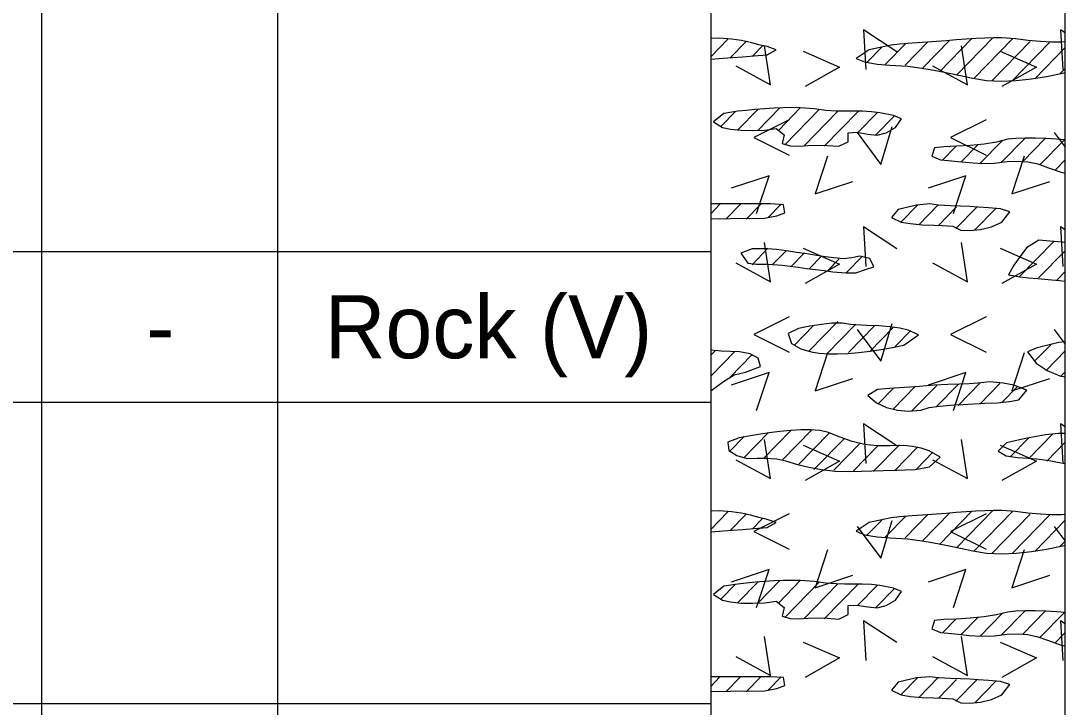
# Model space of a CAD drawing. Extents: x -0.01 to 0.83, y -0.63 to 1.27.
# Drawn here: x 0.7228 to 0.8333, y 0.0953 to 0.1679 of the extents above; entities that cross this region are included whole.
import ezdxf

# ---------------------------------------------------------------- set-up
doc = ezdxf.new("R2010")
doc.units = 0

msp = doc.modelspace()

# ---------------------------------------------------------------- linework, layer by layer
for points in [[(0, 0), (0.83333, 0), (0.83333, 1.275), (0, 1.275)], [(0, 0), (0.83333, 0), (0.83333, 1.275), (0, 1.275)], [(0, 0), (0.83333, 0), (0.83333, 1.275), (0, 1.275)], [(0, 0), (0.83333, 0), (0.83333, 1.275), (0, 1.275)], [(0, 0), (0.83333, 0), (0.83333, 1.275), (0, 1.275)], [(0.79583, 0.16382), (0.79715, 0.16393), (0.79814, 0.16401), (0.79922, 0.16408), (0.80039, 0.16417), (0.80179, 0.16429), (0.80275, 0.16481), (0.80179, 0.16515), (0.80091, 0.16536), (0.80003, 0.16558), (0.79909, 0.16579), (0.79803, 0.16595), (0.79677, 0.16605), (0.79583, 0.16603)], [(0.82816, 0.16158), (0.82978, 0.16174), (0.83137, 0.162), (0.8329, 0.16231), (0.83333, 0.16241), (0.83333, 0.16565), (0.83295, 0.16562), (0.83188, 0.16564), (0.83071, 0.16569), (0.82938, 0.1658), (0.82807, 0.16597), (0.82662, 0.16609), (0.82576, 0.16609), (0.82484, 0.16606), (0.82387, 0.16601), (0.82286, 0.16594), (0.82182, 0.16586), (0.82077, 0.16578), (0.81973, 0.1657), (0.81872, 0.16562), (0.81715, 0.16552), (0.81579, 0.16543), (0.81491, 0.1653), (0.81357, 0.16502), (0.8126, 0.16481), (0.81121, 0.16389), (0.8121, 0.16353), (0.81345, 0.16329), (0.81479, 0.1632), (0.81668, 0.16309), (0.81818, 0.16289), (0.81905, 0.16275), (0.82, 0.16257), (0.82107, 0.16235), (0.82225, 0.1621), (0.82357, 0.16181), (0.82501, 0.16158), (0.82656, 0.16151)], [(0.79708, 0.15659), (0.79794, 0.15642), (0.79904, 0.1563), (0.80028, 0.15627), (0.80156, 0.15632), (0.80274, 0.15648), (0.80361, 0.15582), (0.80338, 0.15492), (0.80422, 0.15465), (0.80517, 0.15463), (0.80613, 0.15469), (0.8072, 0.15472), (0.80818, 0.15469), (0.80939, 0.15461), (0.81037, 0.15508), (0.81038, 0.15603), (0.8113, 0.15609), (0.81244, 0.1559), (0.81346, 0.1558), (0.81438, 0.15605), (0.81539, 0.15659), (0.81601, 0.15751), (0.81517, 0.15788), (0.81374, 0.15815), (0.81285, 0.15825), (0.81187, 0.15831), (0.81, 0.15831), (0.8091, 0.15833), (0.808, 0.1584), (0.80678, 0.15856), (0.8053, 0.15869), (0.80443, 0.1587), (0.80349, 0.15868), (0.80251, 0.15864), (0.80152, 0.15858), (0.80054, 0.1585), (0.79959, 0.15841), (0.7987, 0.15831), (0.79722, 0.15809), (0.79614, 0.15721)], [(0.83241, 0.15537), (0.83129, 0.15544), (0.83017, 0.15548), (0.8291, 0.15548), (0.82811, 0.15544), (0.82728, 0.15535), (0.82608, 0.15505), (0.82476, 0.15483), (0.8233, 0.15469), (0.82183, 0.15461), (0.82051, 0.15455), (0.81951, 0.15445), (0.81922, 0.15358), (0.82013, 0.15317), (0.82097, 0.15311), (0.822, 0.15301), (0.82318, 0.15288), (0.82448, 0.1528), (0.82584, 0.15282), (0.82719, 0.15299), (0.82836, 0.15305), (0.8294, 0.15297), (0.83043, 0.15274), (0.83156, 0.15235), (0.83291, 0.15186), (0.83333, 0.15178), (0.83333, 0.1553)], [(0.79583, 0.14696), (0.79676, 0.14695), (0.79792, 0.14697), (0.79882, 0.14701), (0.79992, 0.14697), (0.80151, 0.14701), (0.80282, 0.14727), (0.80367, 0.14759), (0.80354, 0.14843), (0.80216, 0.14851), (0.79583, 0.14851)], [(0.81822, 0.14632), (0.81944, 0.14626), (0.82033, 0.14622), (0.82145, 0.14615), (0.82229, 0.14574), (0.82324, 0.14569), (0.82438, 0.1458), (0.82555, 0.14609), (0.82662, 0.14659), (0.82749, 0.14769), (0.82651, 0.14799), (0.82524, 0.14809), (0.82413, 0.14816), (0.82324, 0.14826), (0.82226, 0.14828), (0.82121, 0.1483), (0.81995, 0.1484), (0.81902, 0.14851), (0.81761, 0.14837), (0.81566, 0.14793), (0.81496, 0.14709), (0.81598, 0.1466), (0.81695, 0.14643)], [(0.80066, 0.14216), (0.80188, 0.14215), (0.80339, 0.14203), (0.80423, 0.14193), (0.8051, 0.14182), (0.806, 0.1417), (0.80692, 0.14158), (0.80784, 0.14146), (0.80875, 0.14135), (0.81014, 0.14121), (0.81119, 0.14122), (0.81222, 0.14157), (0.81308, 0.14185), (0.81267, 0.14275), (0.8116, 0.143), (0.81075, 0.1428), (0.80989, 0.14272), (0.80885, 0.1428), (0.80799, 0.14291), (0.80703, 0.14306), (0.806, 0.14322), (0.80492, 0.14339), (0.80384, 0.14354), (0.8028, 0.14368), (0.80182, 0.14377), (0.8002, 0.14378), (0.79901, 0.1433), (0.79974, 0.14226)], [(0.83305, 0.14446), (0.83171, 0.14458), (0.83054, 0.14468), (0.82925, 0.14386), (0.82857, 0.14294), (0.82792, 0.14205), (0.82735, 0.14103), (0.82858, 0.1408), (0.82945, 0.1407), (0.83045, 0.14061), (0.83155, 0.14051), (0.83272, 0.14041), (0.83333, 0.14036), (0.83333, 0.14445)], [(0.81233, 0.13565), (0.81063, 0.13577), (0.80977, 0.13591), (0.8086, 0.13591), (0.80755, 0.13577), (0.80632, 0.13557), (0.80513, 0.13533), (0.80403, 0.13481), (0.80436, 0.13375), (0.80536, 0.13318), (0.80647, 0.13288), (0.8073, 0.13273), (0.80824, 0.13265), (0.80926, 0.13265), (0.81035, 0.1327), (0.81149, 0.1328), (0.81267, 0.13295), (0.81386, 0.13313), (0.81506, 0.13334), (0.81625, 0.13358), (0.81783, 0.13466), (0.81673, 0.13516), (0.81585, 0.13536), (0.8148, 0.13552), (0.81361, 0.13562)], [(0.83265, 0.13384), (0.83136, 0.13353), (0.83028, 0.13326), (0.82934, 0.13286), (0.83026, 0.13166), (0.83142, 0.1309), (0.83279, 0.13032), (0.83333, 0.13022), (0.83333, 0.13393)], [(0.79583, 0.12875), (0.79719, 0.12974), (0.79831, 0.13044), (0.79951, 0.13071), (0.80111, 0.13131), (0.80086, 0.13219), (0.80002, 0.13267), (0.79889, 0.13286), (0.79791, 0.13289), (0.79694, 0.13295), (0.79583, 0.13303)], [(0.82537, 0.12969), (0.82408, 0.12954), (0.82319, 0.12948), (0.82214, 0.12946), (0.82091, 0.12942), (0.81947, 0.12933), (0.81792, 0.12921), (0.81632, 0.12909), (0.81475, 0.129), (0.81348, 0.1289), (0.81247, 0.12826), (0.81337, 0.12749), (0.81444, 0.12699), (0.81561, 0.1267), (0.81675, 0.1266), (0.81807, 0.12671), (0.81896, 0.12698), (0.82003, 0.12713), (0.82157, 0.12725), (0.82253, 0.12731), (0.82362, 0.12737), (0.82483, 0.12743), (0.82618, 0.12749), (0.82745, 0.1276), (0.82842, 0.12778), (0.82927, 0.12883), (0.82791, 0.12935), (0.82679, 0.12955)], [(0.79885, 0.12378), (0.79763, 0.12332), (0.79773, 0.12242), (0.79859, 0.1219), (0.7997, 0.1216), (0.80074, 0.12161), (0.80165, 0.12163), (0.80281, 0.12154), (0.80377, 0.12134), (0.80486, 0.12099), (0.80606, 0.12069), (0.80751, 0.12042), (0.80905, 0.12023), (0.81052, 0.1202), (0.81177, 0.12026), (0.81289, 0.1203), (0.81408, 0.12033), (0.81553, 0.12037), (0.81642, 0.1204), (0.81745, 0.12043), (0.81897, 0.12071), (0.82011, 0.12174), (0.81896, 0.12241), (0.8181, 0.12268), (0.81717, 0.12287), (0.81626, 0.12298), (0.81479, 0.12292), (0.81343, 0.12292), (0.8121, 0.12307), (0.8108, 0.12338), (0.80953, 0.12384), (0.8082, 0.12439), (0.80736, 0.12455), (0.8064, 0.12462), (0.80536, 0.12462), (0.80427, 0.12456), (0.80314, 0.12445), (0.80201, 0.12431), (0.8009, 0.12414), (0.79984, 0.12396)], [(0.83263, 0.12423), (0.83126, 0.12409), (0.82969, 0.12382), (0.82883, 0.12365), (0.82712, 0.12324), (0.82623, 0.12237), (0.82708, 0.12188), (0.82831, 0.12169), (0.82941, 0.12163), (0.83033, 0.12154), (0.83165, 0.12136), (0.83253, 0.12121), (0.83333, 0.12107), (0.83333, 0.12422)], [(0.79583, 0.11382), (0.79715, 0.11393), (0.79814, 0.11401), (0.79922, 0.11408), (0.80039, 0.11417), (0.80179, 0.11429), (0.80275, 0.11481), (0.80179, 0.11515), (0.80091, 0.11536), (0.80003, 0.11558), (0.79909, 0.11579), (0.79803, 0.11595), (0.79677, 0.11605), (0.79583, 0.11603)], [(0.82816, 0.11158), (0.82978, 0.11174), (0.83137, 0.112), (0.8329, 0.11231), (0.83333, 0.11241), (0.83333, 0.11565), (0.83295, 0.11562), (0.83188, 0.11564), (0.83071, 0.11569), (0.82938, 0.1158), (0.82807, 0.11597), (0.82662, 0.11609), (0.82576, 0.11609), (0.82484, 0.11606), (0.82387, 0.11601), (0.82286, 0.11594), (0.82182, 0.11586), (0.82077, 0.11578), (0.81973, 0.1157), (0.81872, 0.11562), (0.81715, 0.11552), (0.81579, 0.11543), (0.81491, 0.1153), (0.81357, 0.11502), (0.8126, 0.11481), (0.81121, 0.11389), (0.8121, 0.11353), (0.81345, 0.11329), (0.81479, 0.1132), (0.81668, 0.11309), (0.81818, 0.11289), (0.81905, 0.11275), (0.82, 0.11257), (0.82107, 0.11235), (0.82225, 0.1121), (0.82357, 0.11181), (0.82501, 0.11158), (0.82656, 0.11151)], [(0.79708, 0.10659), (0.79794, 0.10642), (0.79904, 0.1063), (0.80028, 0.10627), (0.80156, 0.10632), (0.80274, 0.10648), (0.80361, 0.10582), (0.80338, 0.10492), (0.80422, 0.10465), (0.80517, 0.10463), (0.80613, 0.10469), (0.8072, 0.10472), (0.80818, 0.10469), (0.80939, 0.10461), (0.81037, 0.10508), (0.81038, 0.10603), (0.8113, 0.10609), (0.81244, 0.1059), (0.81346, 0.1058), (0.81438, 0.10605), (0.81539, 0.10659), (0.81601, 0.10751), (0.81517, 0.10788), (0.81374, 0.10815), (0.81285, 0.10825), (0.81187, 0.10831), (0.81, 0.10831), (0.8091, 0.10833), (0.808, 0.1084), (0.80678, 0.10856), (0.8053, 0.10869), (0.80443, 0.1087), (0.80349, 0.10868), (0.80251, 0.10864), (0.80152, 0.10858), (0.80054, 0.1085), (0.79959, 0.10841), (0.7987, 0.10831), (0.79722, 0.10809), (0.79614, 0.10721)], [(0.83241, 0.10537), (0.83129, 0.10544), (0.83017, 0.10548), (0.8291, 0.10548), (0.82811, 0.10544), (0.82728, 0.10535), (0.82608, 0.10505), (0.82476, 0.10483), (0.8233, 0.10469), (0.82183, 0.10461), (0.82051, 0.10455), (0.81951, 0.10445), (0.81922, 0.10358), (0.82013, 0.10317), (0.82097, 0.10311), (0.822, 0.10301), (0.82318, 0.10288), (0.82448, 0.1028), (0.82584, 0.10282), (0.82719, 0.10299), (0.82836, 0.10305), (0.8294, 0.10297), (0.83043, 0.10274), (0.83156, 0.10235), (0.83291, 0.10186), (0.83333, 0.10178), (0.83333, 0.1053)], [(0.79583, 0.09696), (0.79676, 0.09695), (0.79792, 0.09697), (0.79882, 0.09701), (0.79992, 0.09697), (0.80151, 0.09701), (0.80282, 0.09727), (0.80367, 0.09759), (0.80354, 0.09843), (0.80216, 0.09851), (0.79583, 0.09851)], [(0.81822, 0.09632), (0.81944, 0.09626), (0.82033, 0.09622), (0.82145, 0.09615), (0.82229, 0.09574), (0.82324, 0.09569), (0.82438, 0.0958), (0.82555, 0.09609), (0.82662, 0.09659), (0.82749, 0.09769), (0.82651, 0.09799), (0.82524, 0.09809), (0.82413, 0.09816), (0.82324, 0.09826), (0.82226, 0.09828), (0.82121, 0.0983), (0.81995, 0.0984), (0.81902, 0.09851), (0.81761, 0.09837), (0.81566, 0.09793), (0.81496, 0.09709), (0.81598, 0.0966), (0.81695, 0.09643)]]:
    msp.add_lwpolyline(points, close=True)
for points in [[(0.725, 1.22083), (0.725, -0.62183)], [(0.75, 1.22083), (0.75, -0.62183)], [(0.75, 1.22083), (0.75, -0.62183)], [(0.79583, 1.22083), (0.79583, -0.62183)], [(0.725, 1.20833), (0.725, -0.62183)], [(0.83333, -0.62183), (0.83333, 1.13843)], [(0.81551, 0.16461), (0.81201, 0.16692), (0.81226, 0.16273)], [(0.83333, 0.1666), (0.83284, 0.16692), (0.83309, 0.16273)], [(0.79765, 0.16594), (0.79583, 0.16407)], [(0.81829, 0.16292), (0.82114, 0.16584)], [(0.82004, 0.1625), (0.82346, 0.166)], [(0.82569, 0.16608), (0.82184, 0.16213)], [(0.82775, 0.16598), (0.8237, 0.16183)], [(0.7996, 0.16572), (0.79786, 0.16394)], [(0.79847, 0.16313), (0.80215, 0.16113), (0.80153, 0.16525)], [(0.8013, 0.16524), (0.80027, 0.16419)], [(0.80562, 0.16467), (0.80946, 0.16299), (0.80581, 0.16093)], [(0.81392, 0.16508), (0.81235, 0.16348)], [(0.8143, 0.16326), (0.8165, 0.16551)], [(0.8164, 0.16319), (0.81879, 0.16565)], [(0.8193, 0.16313), (0.82299, 0.16113), (0.82236, 0.16525)], [(0.82964, 0.1657), (0.82557, 0.16153)], [(0.82645, 0.16467), (0.83029, 0.16299), (0.82664, 0.16093)], [(0.83173, 0.16563), (0.82774, 0.16154)], [(0.83333, 0.16506), (0.83012, 0.16176)], [(0.83281, 0.16231), (0.83333, 0.16284)], [(0.79844, 0.15828), (0.79691, 0.15671)], [(0.79871, 0.15634), (0.80085, 0.15853)], [(0.80083, 0.15629), (0.80311, 0.15863)], [(0.80534, 0.15871), (0.80299, 0.15629)], [(0.80367, 0.15478), (0.80732, 0.15852)], [(0.80571, 0.15466), (0.80924, 0.15828)], [(0.81142, 0.15829), (0.80785, 0.15464)], [(0.81141, 0.15607), (0.81348, 0.15819)], [(0.80412, 0.15741), (0.80038, 0.15554), (0.80412, 0.15366)], [(0.81528, 0.15783), (0.81331, 0.15581)], [(0.82496, 0.15741), (0.82121, 0.15554), (0.82496, 0.15366)], [(0.81134, 0.15607), (0.81384, 0.1527), (0.81503, 0.1567)], [(0.83217, 0.15607), (0.83333, 0.15451)], [(0.82233, 0.15298), (0.82408, 0.15476)], [(0.82433, 0.15281), (0.82666, 0.1552)], [(0.82909, 0.15548), (0.82656, 0.15289)], [(0.82885, 0.15301), (0.83122, 0.15544)], [(0.83325, 0.15531), (0.83065, 0.15265)], [(0.82035, 0.15315), (0.82176, 0.1546)], [(0.80818, 0.15358), (0.80687, 0.14958), (0.81087, 0.1509)], [(0.82901, 0.15358), (0.8277, 0.14958), (0.8317, 0.1509)], [(0.83333, 0.15318), (0.83227, 0.15209)], [(0.80069, 0.1475), (0.802, 0.1515), (0.798, 0.15019)], [(0.82152, 0.1475), (0.82284, 0.1515), (0.81884, 0.15019)], [(0.79583, 0.14748), (0.79681, 0.14848)], [(0.79898, 0.1485), (0.79747, 0.14695)], [(0.80116, 0.14852), (0.79959, 0.14691)], [(0.80328, 0.14848), (0.80188, 0.14704)], [(0.8177, 0.14837), (0.81596, 0.14659)], [(0.81988, 0.14839), (0.81785, 0.14632)], [(0.82185, 0.1482), (0.81997, 0.14628)], [(0.824, 0.14819), (0.82178, 0.14591)], [(0.82601, 0.14803), (0.82378, 0.14576)], [(0.81551, 0.14378), (0.81201, 0.14609), (0.81226, 0.1419)], [(0.83333, 0.14577), (0.83284, 0.14609), (0.83309, 0.1419)], [(0.79847, 0.14229), (0.80215, 0.14029), (0.80153, 0.14442)], [(0.80188, 0.14382), (0.8002, 0.14209)], [(0.80562, 0.14384), (0.80946, 0.14216), (0.80581, 0.14009)], [(0.8193, 0.14229), (0.82299, 0.14029), (0.82236, 0.14442)], [(0.82645, 0.14384), (0.83029, 0.14216), (0.82664, 0.14009)], [(0.83217, 0.14459), (0.82844, 0.14077)], [(0.70417, 0.1435), (0.725, 0.1435)], [(0.725, 0.1435), (0.75, 0.1435)], [(0.75, 0.1435), (0.79583, 0.1435)], [(0.8038, 0.14357), (0.80237, 0.14211)], [(0.80575, 0.14335), (0.80429, 0.14186)], [(0.80758, 0.14302), (0.80627, 0.14168)], [(0.80941, 0.14269), (0.80816, 0.1414)], [(0.81188, 0.143), (0.81016, 0.14124)], [(0.83333, 0.14357), (0.83052, 0.14069)], [(0.83333, 0.14136), (0.83245, 0.14045)], [(0.80412, 0.13658), (0.80038, 0.13471), (0.80412, 0.13283)], [(0.80626, 0.13297), (0.80928, 0.13607)], [(0.82496, 0.13658), (0.82121, 0.13471), (0.82496, 0.13283)], [(0.80465, 0.13354), (0.80667, 0.13561)], [(0.80809, 0.13264), (0.81111, 0.13574)], [(0.81041, 0.1328), (0.81318, 0.13564)], [(0.81134, 0.13524), (0.81384, 0.13187), (0.81503, 0.13587)], [(0.81264, 0.13288), (0.81518, 0.13548)], [(0.81536, 0.13345), (0.81699, 0.13512)], [(0.83217, 0.13524), (0.83333, 0.13368)], [(0.7963, 0.13299), (0.79583, 0.13251)], [(0.79834, 0.13286), (0.79583, 0.1303)], [(0.80818, 0.13275), (0.80687, 0.12875), (0.81087, 0.13006)], [(0.82901, 0.13275), (0.8277, 0.12875), (0.8317, 0.13006)], [(0.8301, 0.13188), (0.83184, 0.13366)], [(0.83131, 0.1309), (0.83333, 0.13298)], [(0.79786, 0.13016), (0.80023, 0.13259)], [(0.80069, 0.12667), (0.802, 0.13067), (0.798, 0.12936)], [(0.82152, 0.12667), (0.82284, 0.13067), (0.81884, 0.12936)], [(0.83285, 0.13027), (0.83333, 0.13076)], [(0.81709, 0.12658), (0.81974, 0.1293)], [(0.8197, 0.12704), (0.82203, 0.12943)], [(0.82202, 0.1272), (0.8243, 0.12954)], [(0.82431, 0.12733), (0.82644, 0.12953)], [(0.81519, 0.12906), (0.81354, 0.12736)], [(0.81514, 0.1268), (0.81748, 0.12919)], [(0.82663, 0.1275), (0.82834, 0.12925)], [(0.70417, 0.12756), (0.725, 0.12756)], [(0.725, 0.12756), (0.75, 0.12756)], [(0.75, 0.12756), (0.79583, 0.12756)], [(0.81551, 0.12294), (0.81201, 0.12526), (0.81226, 0.12107)], [(0.83333, 0.12493), (0.83284, 0.12526), (0.83309, 0.12107)], [(0.79938, 0.12392), (0.79786, 0.12237)], [(0.79933, 0.12165), (0.80195, 0.12434)], [(0.80142, 0.12158), (0.8043, 0.12454)], [(0.80653, 0.12461), (0.8034, 0.1214)], [(0.80506, 0.12089), (0.8084, 0.12431)], [(0.83203, 0.12418), (0.82949, 0.12158)], [(0.79847, 0.12146), (0.80215, 0.11946), (0.80153, 0.12359)], [(0.80562, 0.12301), (0.80946, 0.12132), (0.80581, 0.11926)], [(0.80997, 0.12371), (0.80675, 0.12041)], [(0.81164, 0.1232), (0.80884, 0.12034)], [(0.81353, 0.12293), (0.81094, 0.12027)], [(0.81303, 0.12021), (0.81579, 0.12303)], [(0.81534, 0.12036), (0.81768, 0.12276)], [(0.8193, 0.12146), (0.82299, 0.11946), (0.82236, 0.12359)], [(0.82645, 0.12301), (0.83029, 0.12132), (0.82664, 0.11926)], [(0.82751, 0.12176), (0.82945, 0.12375)], [(0.83138, 0.1213), (0.83333, 0.1233)], [(0.8176, 0.12047), (0.81934, 0.12225)], [(0.83333, 0.12108), (0.83333, 0.12109)], [(0.82569, 0.11608), (0.82184, 0.11213)], [(0.79765, 0.11594), (0.79583, 0.11407)], [(0.7996, 0.11572), (0.79786, 0.11394)], [(0.8013, 0.11524), (0.80027, 0.11419)], [(0.80412, 0.11575), (0.80038, 0.11387), (0.80412, 0.112)], [(0.81134, 0.11441), (0.81384, 0.11103), (0.81503, 0.11503)], [(0.81392, 0.11508), (0.81235, 0.11348)], [(0.8143, 0.11326), (0.8165, 0.11551)], [(0.8164, 0.11319), (0.81879, 0.11565)], [(0.81829, 0.11292), (0.82114, 0.11584)], [(0.82004, 0.1125), (0.82346, 0.116)], [(0.82496, 0.11575), (0.82121, 0.11387), (0.82496, 0.112)], [(0.82775, 0.11598), (0.8237, 0.11183)], [(0.82964, 0.1157), (0.82557, 0.11153)], [(0.83173, 0.11563), (0.82774, 0.11154)], [(0.83333, 0.11506), (0.83012, 0.11176)], [(0.83217, 0.11441), (0.83333, 0.11285)], [(0.83281, 0.11231), (0.83333, 0.11284)], [(0.80818, 0.11192), (0.80687, 0.10792), (0.81087, 0.10923)], [(0.82901, 0.11192), (0.8277, 0.10792), (0.8317, 0.10923)], [(0.80069, 0.10584), (0.802, 0.10984), (0.798, 0.10852)], [(0.82152, 0.10584), (0.82284, 0.10984), (0.81884, 0.10852)], [(0.79871, 0.10634), (0.80085, 0.10853)], [(0.80083, 0.10629), (0.80311, 0.10863)], [(0.80534, 0.10871), (0.80299, 0.10629)], [(0.80367, 0.10478), (0.80732, 0.10852)], [(0.81142, 0.10829), (0.80785, 0.10464)], [(0.79844, 0.10828), (0.79691, 0.10671)], [(0.80571, 0.10466), (0.80924, 0.10828)], [(0.81141, 0.10607), (0.81348, 0.1082)], [(0.81528, 0.10783), (0.81331, 0.10581)], [(0.82433, 0.10281), (0.82666, 0.1052)], [(0.82909, 0.10548), (0.82656, 0.10289)], [(0.82885, 0.10301), (0.83122, 0.10544)], [(0.83325, 0.10531), (0.83065, 0.10265)], [(0.81551, 0.10211), (0.81201, 0.10442), (0.81226, 0.10023)], [(0.82035, 0.10315), (0.82176, 0.1046)], [(0.82233, 0.10298), (0.82408, 0.10476)], [(0.83333, 0.1041), (0.83284, 0.10442), (0.83309, 0.10023)], [(0.83333, 0.10318), (0.83227, 0.10209)], [(0.79847, 0.10063), (0.80215, 0.09863), (0.80153, 0.10275)], [(0.80562, 0.10217), (0.80946, 0.10049), (0.80581, 0.09843)], [(0.8193, 0.10063), (0.82299, 0.09863), (0.82236, 0.10275)], [(0.82645, 0.10217), (0.83029, 0.10049), (0.82664, 0.09843)], [(0.79583, 0.09748), (0.79681, 0.09848)], [(0.79898, 0.0985), (0.79747, 0.09695)], [(0.80116, 0.09852), (0.79959, 0.09691)], [(0.80328, 0.09848), (0.80188, 0.09704)], [(0.8177, 0.09837), (0.81596, 0.09659)], [(0.81988, 0.09839), (0.81785, 0.09632)], [(0.82185, 0.0982), (0.81997, 0.09628)], [(0.824, 0.09819), (0.82178, 0.09591)], [(0.82601, 0.09803), (0.82378, 0.09576)], [(0.70417, 0.09567), (0.725, 0.09567)], [(0.725, 0.09567), (0.75, 0.09567)], [(0.75, 0.09567), (0.79583, 0.09567)]]:
    msp.add_lwpolyline(points)

# ---------------------------------------------------------------- texts
for s, height, p in [('Rock (V)', 0.006667, (0.75497, 0.13219)), ('-', 0.00667, (0.73609, 0.13219))]:
    msp.add_text(s, height=height).set_placement(p)

doc.saveas('drawing.dxf')
